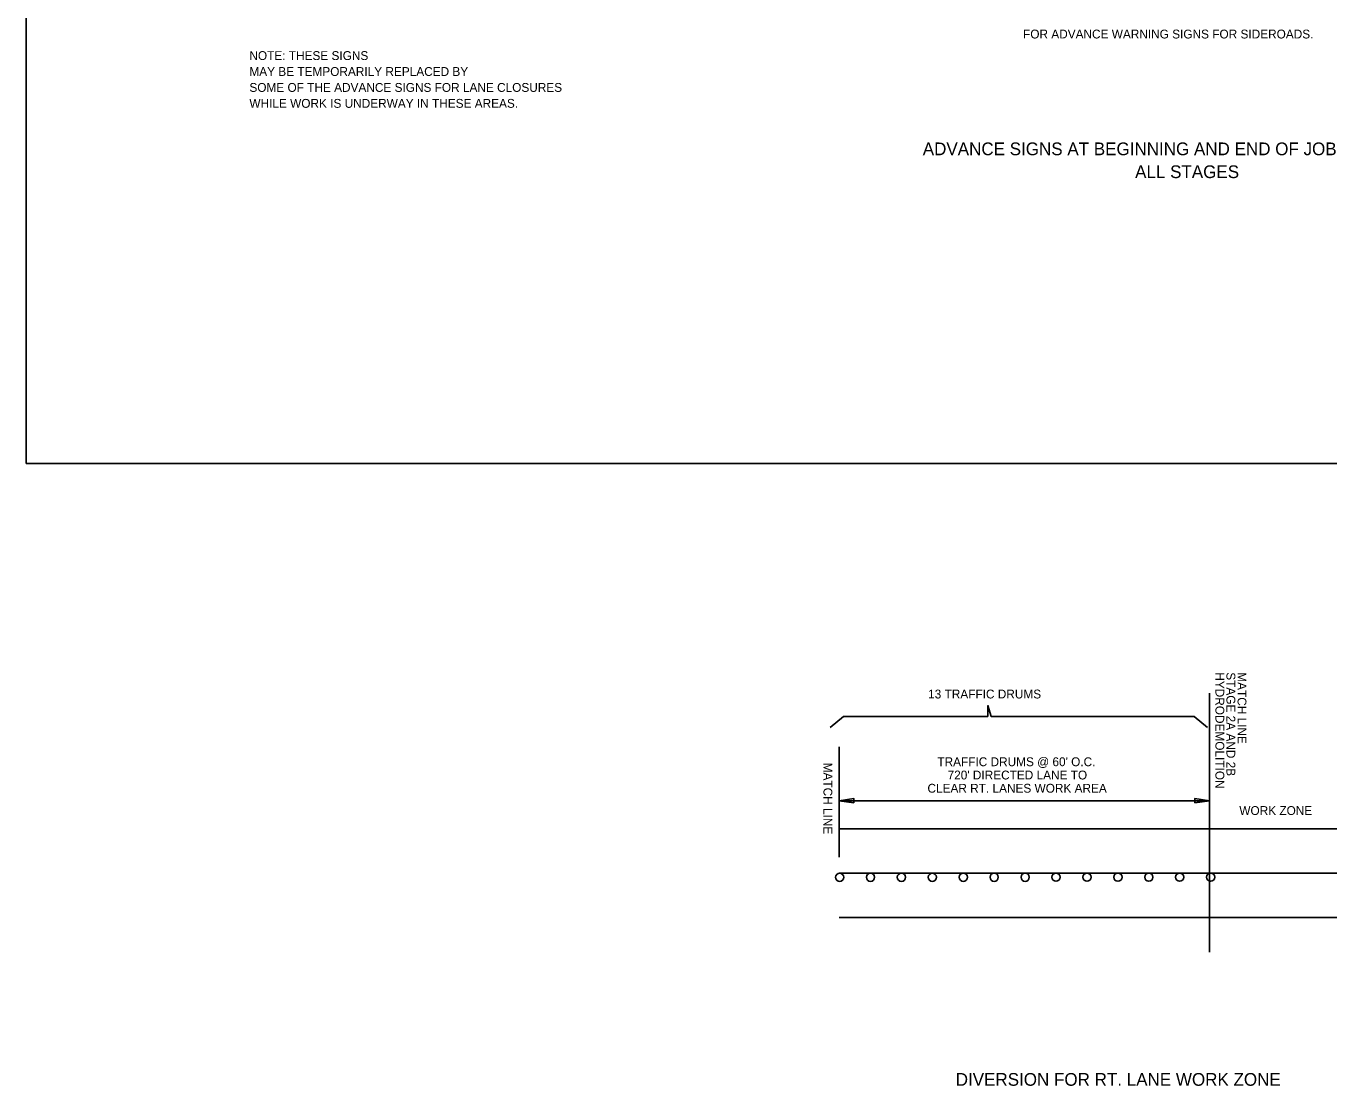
# Model space of a CAD drawing. Extents: x -900 to -62, y -12423 to -11428.
# Drawn here: x -702.6 to -349, y -12421.3 to -12133.7 of the extents above; entities that cross this region are included whole.
import ezdxf

# ---------------------------------------------------------------- set-up
doc = ezdxf.new("R2010")
doc.units = 0
for name, color, linetype in [('1', 7, 'Continuous'), ('Level 1', 7, 'Continuous'), ('R_MOT', 7, 'Continuous')]:
    doc.layers.add(name, color=color, linetype=linetype)

msp = doc.modelspace()

# ---------------------------------------------------------------- linework, layer by layer
at = {"layer": '1'}
for p, q in [((-381.39, -12385.02), (-381.39, -12314.77)), ((-481.93, -12359.3), (-481.93, -12329.3)), ((-381.39, -12343.93), (-481.93, -12343.93)), ((-481.93, -12351.61), (-306.47, -12351.61)), ((-481.93, -12363.61), (-306.47, -12363.61)), ((-481.93, -12375.61), (-306.47, -12375.61))]:
    msp.add_line(p, q, dxfattribs=at)
for points in [[(-484.35, -12324.03), (-480.77, -12321.09), (-441.55, -12321.09)], [(-441.55, -12321.09), (-441.55, -12318.13), (-440.65, -12321.09)], [(-440.65, -12321.09), (-385.53, -12321.09), (-381.95, -12324.03)]]:
    msp.add_lwpolyline(points, dxfattribs=at)
for points in [[(-477.97, -12344.53), (-481.93, -12343.93), (-477.97, -12343.33)], [(-385.35, -12344.53), (-381.39, -12343.93), (-385.35, -12343.33)]]:
    msp.add_lwpolyline(points, close=True, dxfattribs=at)
for centre in [(-481.79, -12364.72), (-473.4, -12364.71), (-465.01, -12364.71), (-456.61, -12364.71), (-448.22, -12364.7), (-439.83, -12364.7), (-431.43, -12364.7), (-423.04, -12364.69), (-414.65, -12364.69), (-406.25, -12364.69), (-397.86, -12364.68), (-389.47, -12364.68), (-381.08, -12364.68)]:
    msp.add_circle(centre, 1.12, dxfattribs=at)
at = {"layer": 'Level 1'}
for p, q in [((-702.63, -12252.44), (-702.63, -11841.52)), ((-62.41, -12252.44), (-702.63, -12252.44))]:
    msp.add_line(p, q, dxfattribs=at)

# ---------------------------------------------------------------- texts
at = {"layer": '1'}
for s, height, p in [('     FOR ADVANCE WARNING SIGNS FOR SIDEROADS.', 2.4, (-436.45, -12137.1)), ('NOTE: THESE SIGNS', 2.4, (-642, -12142.95)), ('MAY BE TEMPORARILY REPLACED BY', 2.4, (-642, -12147.27)), ('SOME OF THE ADVANCE SIGNS FOR LANE CLOSURES', 2.4, (-642, -12151.59)), ('WHILE WORK IS UNDERWAY IN THESE AREAS.', 2.4, (-642, -12155.91)), ('ADVANCE SIGNS AT BEGINNING AND END OF JOB 009916', 3.452, (-459.22, -12168.78)), ('ALL STAGES', 3.452, (-401.58, -12174.99)), ('DIVERSION FOR RT. LANE WORK ZONE', 3.452, (-450.27, -12421.29))]:
    msp.add_text(s, height=height, dxfattribs=at).set_placement(p)
for s, p in [('HYDRODEMOLITION', (-379.78, -12309.09)), ('STAGE 2A AND 2B', (-376.78, -12309.09)), ('MATCH LINE', (-373.77, -12309.09)), ('MATCH LINE', (-486.17, -12333.62))]:
    msp.add_text(s, height=2.4, rotation=270, dxfattribs=at).set_placement(p)
at = {"layer": 'R_MOT'}
for s, height, p in [('13 TRAFFIC DRUMS', 2.4, (-457.76, -12316.19)), ("TRAFFIC DRUMS @ 60' O.C.", 2.3996, (-455.26, -12334.57)), ("720' DIRECTED LANE TO", 2.3996, (-452.48, -12338.17)), ('CLEAR RT. LANES WORK AREA', 2.3996, (-457.94, -12341.76)), ('WORK ZONE', 2.4, (-373.29, -12347.81))]:
    msp.add_text(s, height=height, rotation=360, dxfattribs=at).set_placement(p)

doc.saveas('drawing.dxf')
